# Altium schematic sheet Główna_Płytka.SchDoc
size A0; SheetNumber: 1; SheetTotal: 1
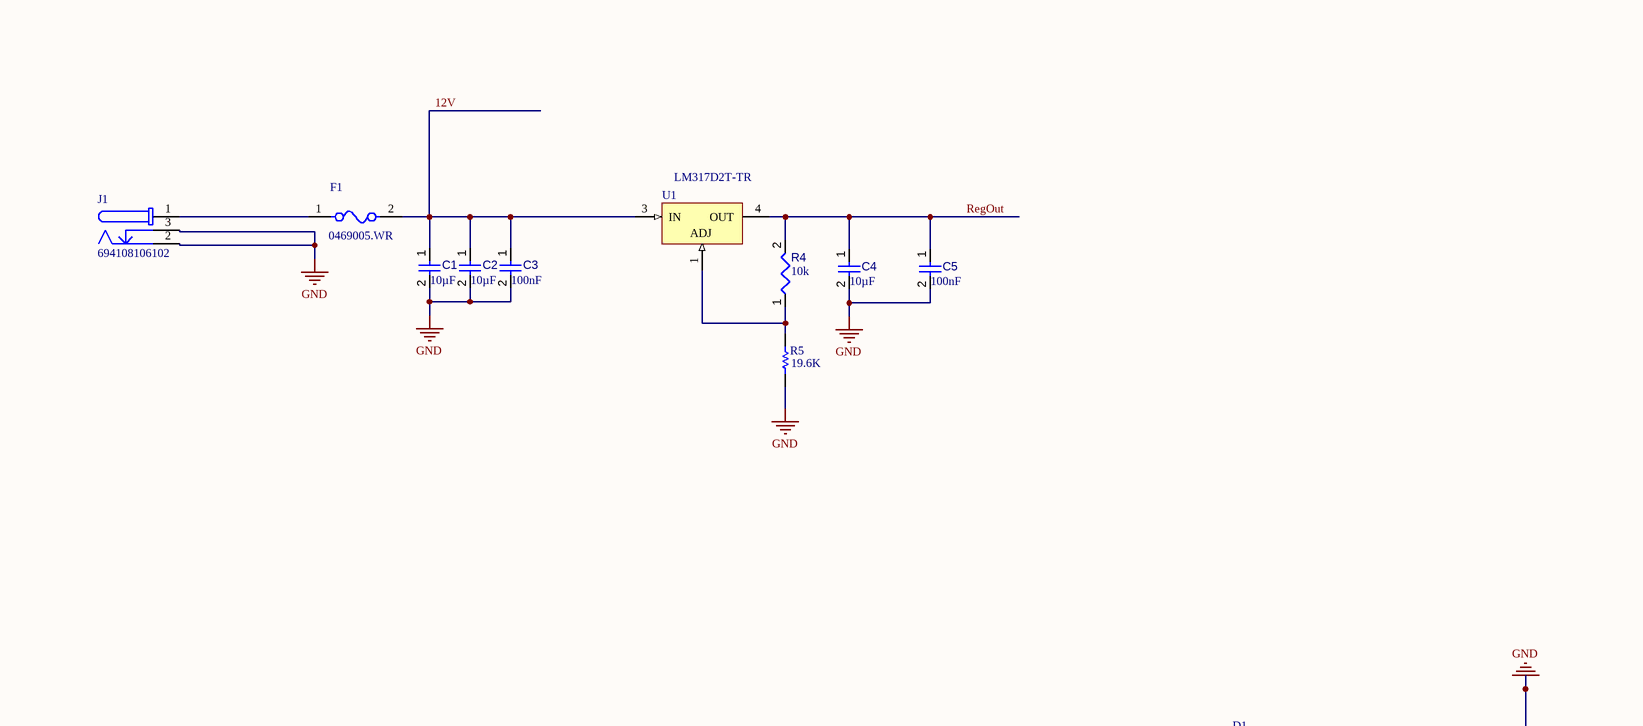
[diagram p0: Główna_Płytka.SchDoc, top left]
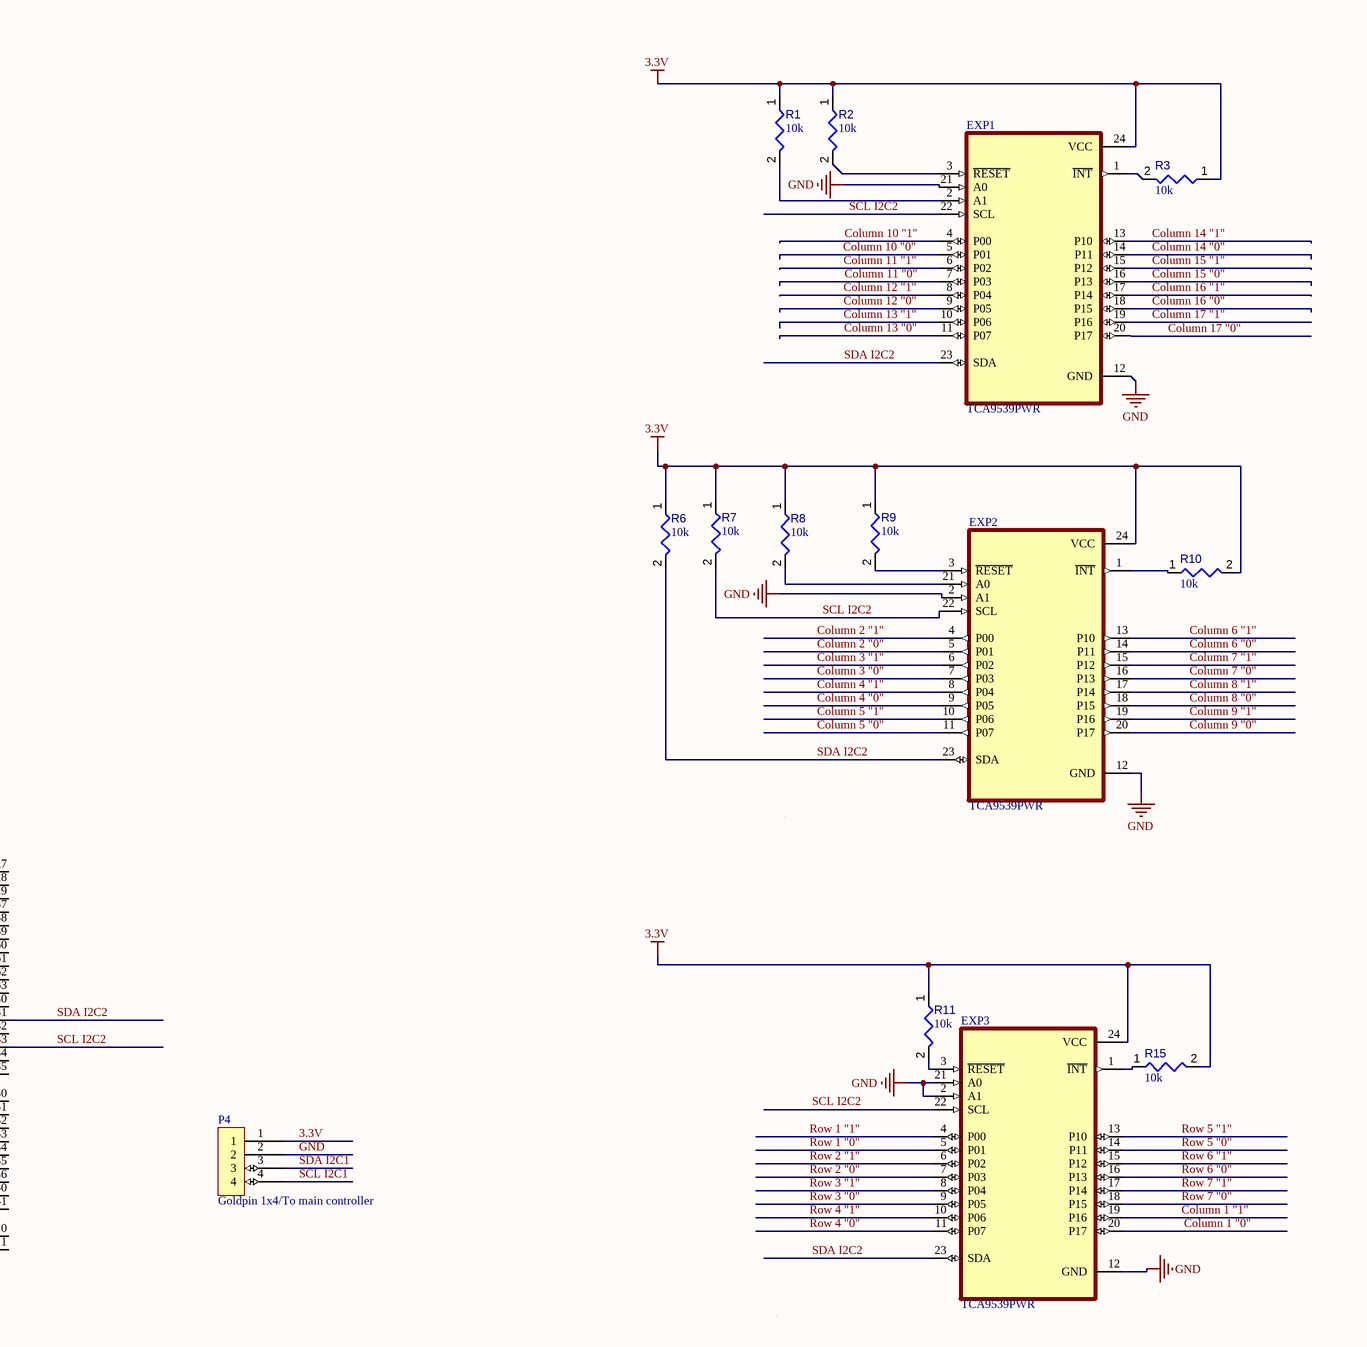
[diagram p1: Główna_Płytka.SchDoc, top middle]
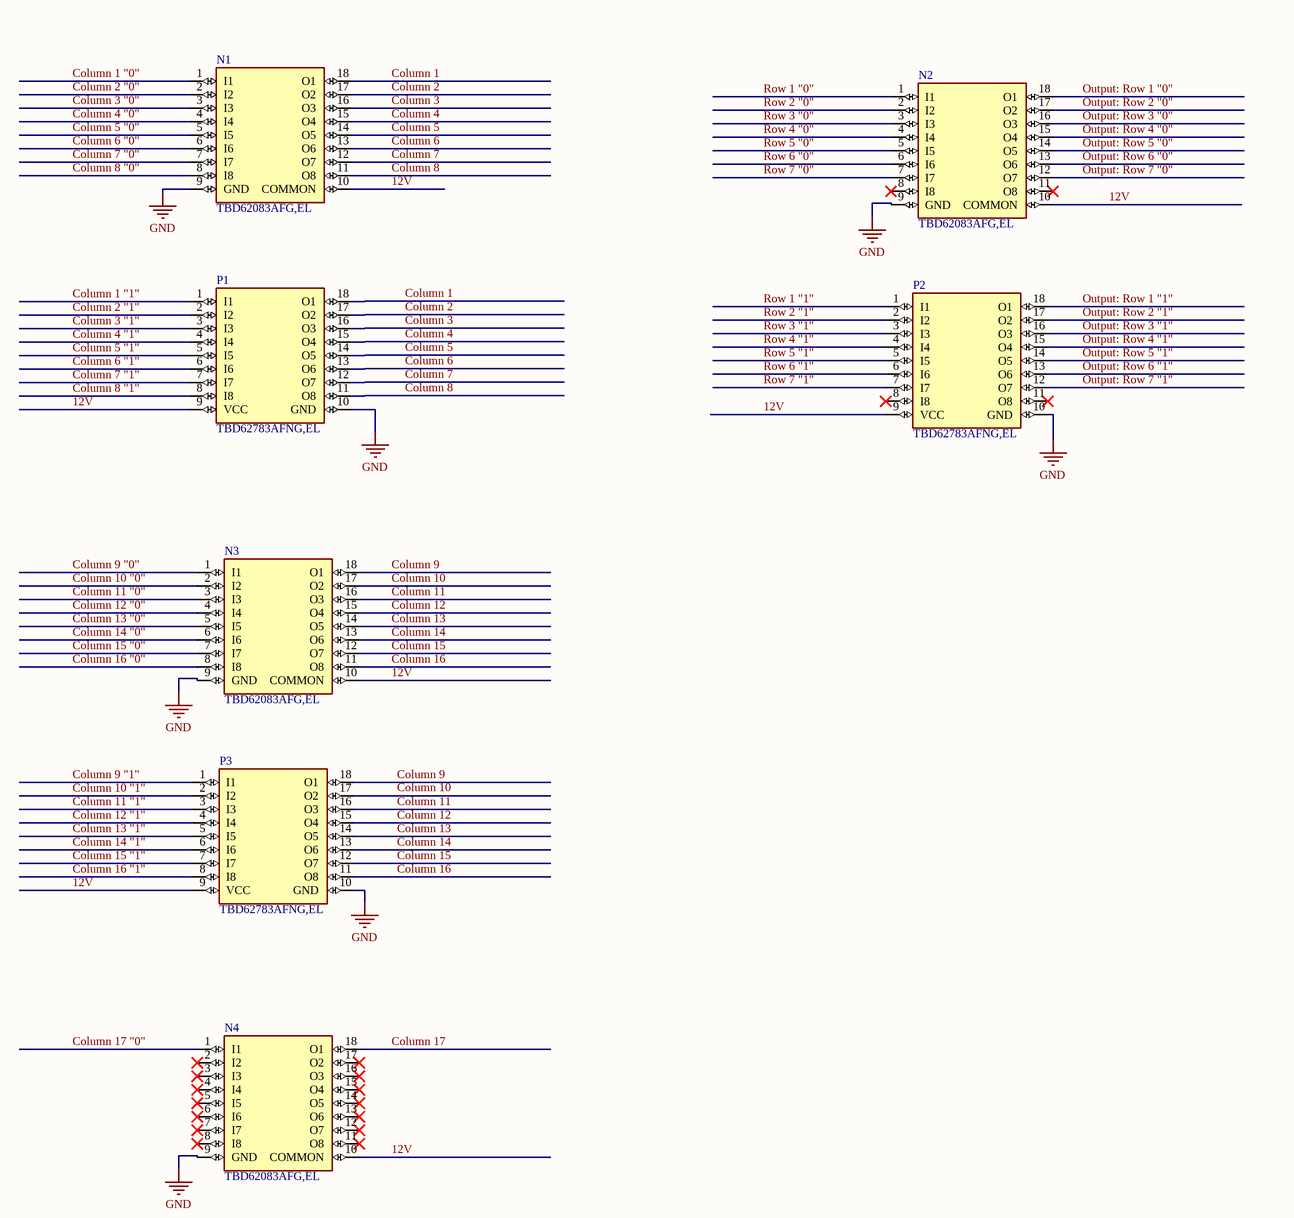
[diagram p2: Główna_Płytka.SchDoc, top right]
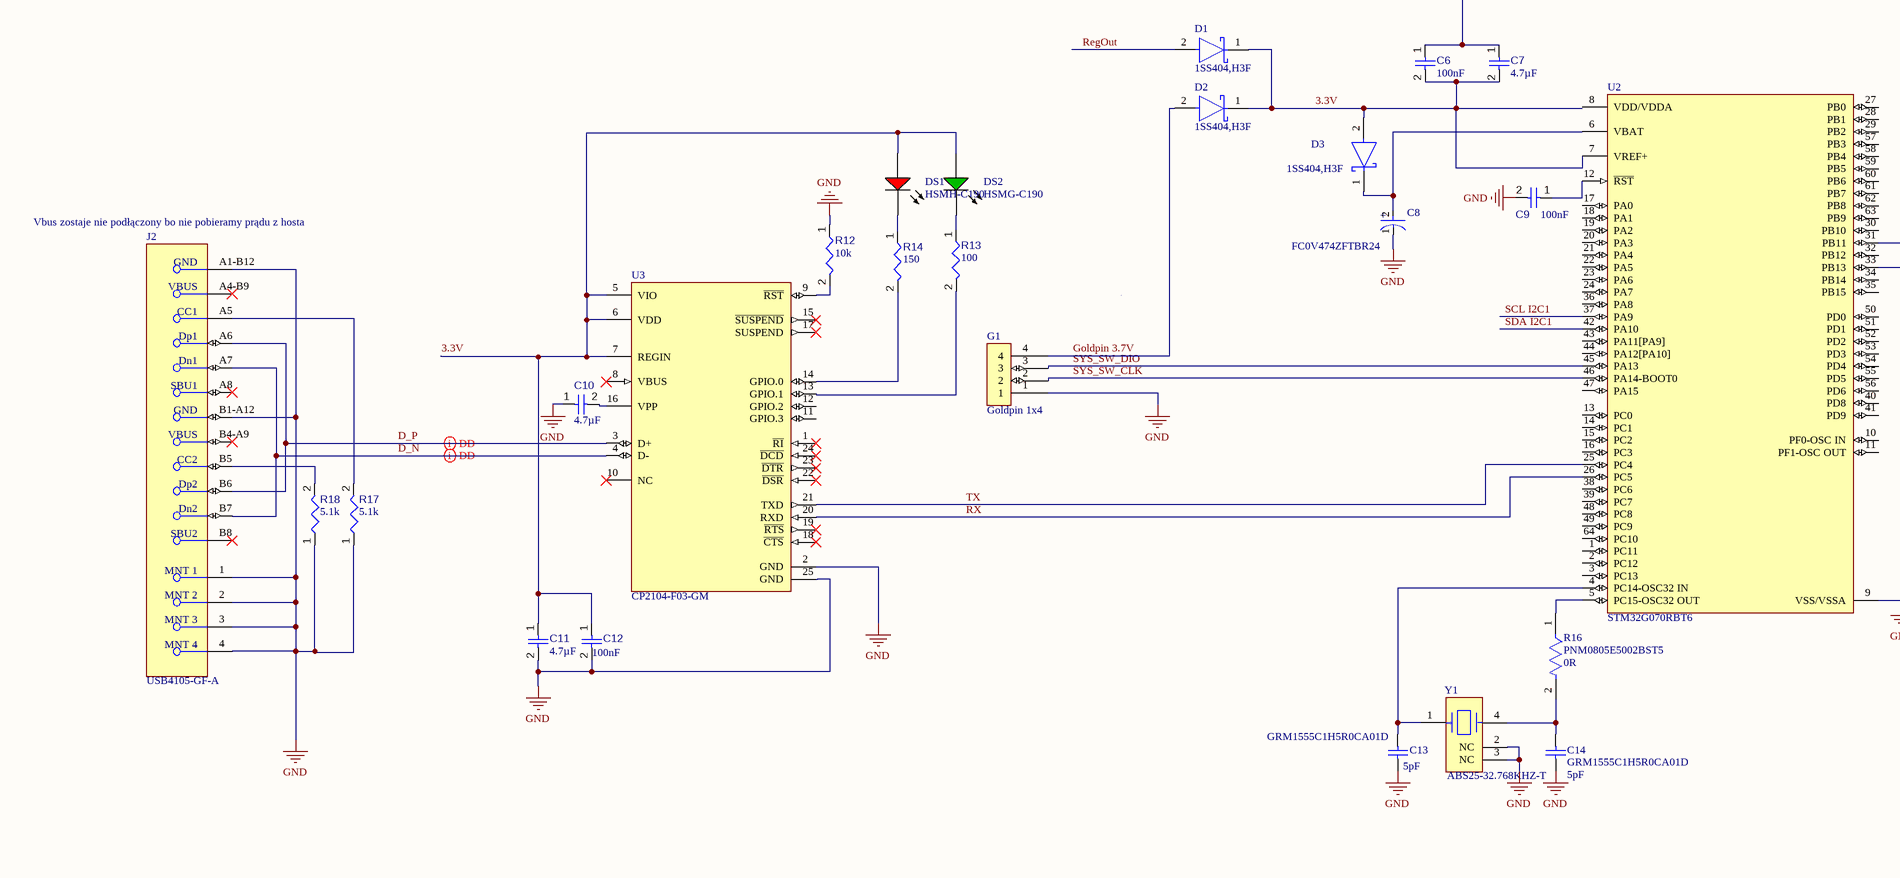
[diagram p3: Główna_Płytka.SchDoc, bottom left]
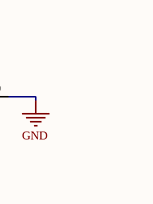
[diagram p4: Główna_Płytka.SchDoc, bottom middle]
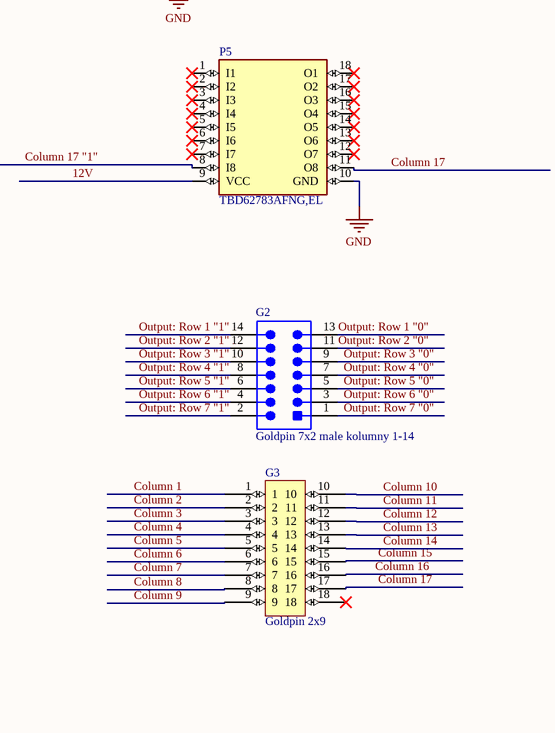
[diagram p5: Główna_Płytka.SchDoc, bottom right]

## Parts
C1  value 10µF  [CAPC0603(1608)100_L]  (hidden comment: Capacitor 10µF +/-20% 10V 0603)
C2  value 10µF  [CAPC0603(1608)100_L]  (hidden comment: Capacitor 10µF +/-20% 10V 0603)
C3  value 100nF  [CAPC0402(1005)60_L]  (hidden comment: Capacitor 100nF +/-20% 50V 0402)
C4  value 10µF  [CAPC0603(1608)100_L]  (hidden comment: Capacitor 10µF +/-20% 10V 0603)
C5  value 100nF  [CAPC0402(1005)60_L]  (hidden comment: Capacitor 100nF +/-20% 50V 0402)
C6  value 100nF  [CAPC0402(1005)60_L]  (hidden comment: Capacitor 100nF +/-20% 10V 0402)
C7  value 4.7µF  [CAPC0603(1608)100_L]  (hidden comment: Capacitor 4.7µF +/-20% 10V 0603)
C8  FC0V474ZFTBR24  [FP-FC0V474ZFTBR24-MFG]
C9  value 100nF  [CAPC0402(1005)60_L]  (hidden comment: Capacitor 100nF +/-20% 50V 0402)
C10  value 4.7µF  [CAPC0603(1608)100_L]  (hidden comment: Capacitor 4.7µF +/-20% 10V 0603)
C11  value 4.7µF  [CAPC0603(1608)100_L]  (hidden comment: Capacitor 4.7µF +/-20% 10V 0603)
C12  value 100nF  [CAPC0402(1005)60_L]  (hidden comment: Capacitor 100nF +/-20% 50V 0402)
C13  GRM1555C1H5R0CA01D  value 5pF  [CAPC1005X55X25LL05T10]
C14  GRM1555C1H5R0CA01D  value 5pF  [CAPC1005X55X25LL05T10]
D1  1SS404,H3F  [FP-SOD-323-MFG]
D2  1SS404,H3F  [FP-SOD-323-MFG]
D3  1SS404,H3F  [FP-SOD-323-MFG]
DS1  HSMH-C190  [AVAG-HSMX-C190_V]
DS2  HSMG-C190  [AVAG-HSMX-C190_V]
EXP1  TCA9539PWR  [SOP65P640X120-24N]
EXP2  TCA9539PWR  [SOP65P640X120-24N]
EXP3  TCA9539PWR  [SOP65P640X120-24N]
F1  0469005.WR  [FP-0469-MFG]
G1  Goldpin 1x4  [Goldpin 1x4-Footprint-1]
G2  Goldpin 7x2 male kolumny 1-14  [HRWN-M20-9980745_V]
G3  Goldpin 2x9  [Goldpin 2x9-Footprint-1]
J1  694108106102  [694108106102]
J2  USB4105-GF-A  [FP-USB4105-GF-A-MFG]
N1  TBD62083AFG,EL  [SOIC127P1030X245-18N]
N2  TBD62083AFG,EL  [SOIC127P1030X245-18N]
N3  TBD62083AFG,EL  [SOIC127P1030X245-18N]
N4  TBD62083AFG,EL  [SOIC127P1030X245-18N]
P1  TBD62783AFNG,EL  [New footprint 1]
P2  TBD62783AFNG,EL  [New footprint 1]
P3  TBD62783AFNG,EL  [New footprint 1]
P4  Goldpin 1x4/To main controller  [Goldpin 1x4-Footprint-1]
P5  TBD62783AFNG,EL  [New footprint 1]
R1  value 10k  [RESC2013X50X35ML15T15]  (hidden comment: Resistor 10k +/-1% 0805 125 mW)
R2  value 10k  [RESC2013X50X35ML15T15]  (hidden comment: Resistor 10k +/-1% 0805 125 mW)
R3  value 10k  [RESC2013X50X35ML15T15]  (hidden comment: Resistor 10k +/-1% 0805 125 mW)
R4  value 10k  [RESC2013X50X35ML15T15]  (hidden comment: Resistor 10k +/-1% 0805 125 mW)
R5  value 19.6K  [RESC1005X40X25NL05T05]  (hidden comment: ERJ-2RKF1962X)
R6  value 10k  [RESC2013X50X35ML15T15]  (hidden comment: Resistor 10k +/-1% 0805 125 mW)
R7  value 10k  [RESC2013X50X35ML15T15]  (hidden comment: Resistor 10k +/-1% 0805 125 mW)
R8  value 10k  [RESC2013X50X35ML15T15]  (hidden comment: Resistor 10k +/-1% 0805 125 mW)
R9  value 10k  [RESC2013X50X35ML15T15]  (hidden comment: Resistor 10k +/-1% 0805 125 mW)
R10  value 10k  [RESC2013X50X35ML15T15]  (hidden comment: Resistor 10k +/-1% 0805 125 mW)
R11  value 10k  [RESC2013X50X35ML15T15]  (hidden comment: Resistor 10k +/-1% 0805 125 mW)
R12  value 10k  [RESC2013X50X35ML15T15]  (hidden comment: Resistor 10k +/-1% 0805 125 mW)
R13  value 100  [RESC2013X50X35ML15T15]  (hidden comment: Resistor 10k +/-1% 0805 125 mW)
R14  value 150  [RESC2013X50X35ML15T15]  (hidden comment: Resistor 10k +/-1% 0805 125 mW)
R15  value 10k  [RESC2013X50X35ML15T15]  (hidden comment: Resistor 10k +/-1% 0805 125 mW)
R16  PNM0805E5002BST5  Resistance: 0R  [FP-PNM0805-MFG]
R17  value 5.1k  [RESC2013X50X35ML15T15]  (hidden comment: Resistor 10k +/-1% 0805 125 mW)
R18  value 5.1k  [RESC2013X50X35ML15T15]  (hidden comment: Resistor 10k +/-1% 0805 125 mW)
U1  LM317D2T-TR  [TO-263_N]
U2  STM32G070RBT6  [FP-LQFP64-5W-MFG]
U3  CP2104-F03-GM  [FP-CP2104-F03-GM-MFG]
Y1  ABS25-32.768KHZ-T  [FP-ABS25-MFG]

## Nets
3.3V: C6.2 C7.2 C11.1 C12.1 D1.1(C) D2.1(C) D3.2(A) DS1.1(A) DS2.1(A) EXP1.24(VCC) EXP2.24(VCC) EXP3.24(VCC) P4.1 R1.1 R2.1 R3.1 R6.1 R7.1 R8.1 R9.1 R10.2 R11.1 R15.2 U2.7(VREF+) U3.5(VIO) U3.6(VDD) U3.7(REGIN)
GND: C1.2 C2.2 C3.2 C4.2 C5.2 C6.1 C7.1 C8.1(C) C9.2 C10.1 C11.2 C12.2 C13.1 C14.1 EXP1.12(GND) EXP1.21(A0) EXP2.2(A1) EXP2.12(GND) EXP3.2(A1) EXP3.12(GND) EXP3.21(A0) G1.1 J1.2 J1.3 J2.1(MNT_1) J2.2(MNT_2) J2.3(MNT_3) J2.4(MNT_4) J2.A1-B12(GND) J2.B1-A12(GND) N1.9(GND) N2.9(GND) N3.9(GND) N4.9(GND) P1.10(GND) P2.10(GND) P3.10(GND) P4.2 P5.10(GND) R5.2 R12.1 R17.1 R18.1 U2.9(VSS/VSSA) U3.2(GND) U3.25(GND) Y1.2(NC) Y1.3(NC)
12V: C1.1 C2.1 C3.1 F1.2 N1.10(COMMON) N2.10(COMMON) N3.10(COMMON) N4.10(COMMON) P1.9(VCC) P2.9(VCC) P3.9(VCC) P5.9(VCC) U1.3(IN)
Column 1: G3.1 N1.18(O1) P1.18(O1)
Column 1 "0": EXP3.20(P17) N1.1(I1)
Column 1 "1": EXP3.19(P16) P1.1(I1)
Column 2: G3.2 N1.17(O2) P1.17(O2)
Column 2 "0": EXP2.5(P01) N1.2(I2)
Column 2 "1": EXP2.4(P00) P1.2(I2)
Column 3: G3.3 N1.16(O3) P1.16(O3)
Column 3 "0": EXP2.7(P03) N1.3(I3)
Column 3 "1": EXP2.6(P02) P1.3(I3)
Column 4: G3.4 N1.15(O4) P1.15(O4)
Column 4 "0": EXP2.9(P05) N1.4(I4)
Column 4 "1": EXP2.8(P04) P1.4(I4)
Column 5: G3.5 N1.14(O5) P1.14(O5)
Column 5 "0": EXP2.11(P07) N1.5(I5)
Column 5 "1": EXP2.10(P06) P1.5(I5)
Column 6: G3.6 N1.13(O6) P1.13(O6)
Column 6 "0": EXP2.14(P11) N1.6(I6)
Column 6 "1": EXP2.13(P10) P1.6(I6)
Column 7: G3.7 N1.12(O7) P1.12(O7)
Column 7 "0": EXP2.16(P13) N1.7(I7)
Column 7 "1": EXP2.15(P12) P1.7(I7)
Column 8: G3.8 N1.11(O8) P1.11(O8)
Column 8 "0": EXP2.18(P15) N1.8(I8)
Column 8 "1": EXP2.17(P14) P1.8(I8)
Column 9: G3.9 N3.18(O1) P3.18(O1)
Column 9 "0": EXP2.20(P17) N3.1(I1)
Column 9 "1": EXP2.19(P16) P3.1(I1)
Column 10: G3.10 N3.17(O2) P3.17(O2)
Column 10 "0": EXP1.5(P01) N3.2(I2)
Column 10 "1": EXP1.4(P00) P3.2(I2)
Column 11: G3.11 N3.16(O3) P3.16(O3)
Column 11 "0": EXP1.7(P03) N3.3(I3)
Column 11 "1": EXP1.6(P02) P3.3(I3)
Column 12: G3.12 N3.15(O4) P3.15(O4)
Column 12 "0": EXP1.9(P05) N3.4(I4)
Column 12 "1": EXP1.8(P04) P3.4(I4)
Column 13: G3.13 N3.14(O5) P3.14(O5)
Column 13 "0": EXP1.11(P07) N3.5(I5)
Column 13 "1": EXP1.10(P06) P3.5(I5)
Column 14: G3.14 N3.13(O6) P3.13(O6)
Column 14 "0": EXP1.14(P11) N3.6(I6)
Column 14 "1": EXP1.13(P10) P3.6(I6)
Column 15: G3.15 N3.12(O7) P3.12(O7)
Column 15 "0": EXP1.16(P13) N3.7(I7)
Column 15 "1": EXP1.15(P12) P3.7(I7)
Column 16: G3.16 N3.11(O8) P3.11(O8)
Column 16 "0": EXP1.18(P15) N3.8(I8)
Column 16 "1": EXP1.17(P14) P3.8(I8)
Column 17: G3.17 N4.18(O1) P5.11(O8)
Column 17 "0": EXP1.20(P17) N4.1(I1)
Column 17 "1": EXP1.19(P16) P5.8(I8)
D_N: J2.A7(Dn1) J2.B7(Dn2) U3.4(D-)
D_P: J2.A6(Dp1) J2.B6(Dp2) U3.3(D+)
Goldpin 3.7V: D2.2(A) G1.4
Output: Row 1 "0": G2.13 N2.18(O1)
Output: Row 1 "1": G2.14 P2.18(O1)
Output: Row 2 "0": G2.11 N2.17(O2)
Output: Row 2 "1": G2.12 P2.17(O2)
Output: Row 3 "0": G2.9 N2.16(O3)
Output: Row 3 "1": G2.10 P2.16(O3)
Output: Row 4 "0": G2.7 N2.15(O4)
Output: Row 4 "1": G2.8 P2.15(O4)
Output: Row 5 "0": G2.5 N2.14(O5)
Output: Row 5 "1": G2.6 P2.14(O5)
Output: Row 6 "0": G2.3 N2.13(O6)
Output: Row 6 "1": G2.4 P2.13(O6)
Output: Row 7 "0": G2.1 N2.12(O7)
Output: Row 7 "1": G2.2 P2.12(O7)
RegOut: C4.1 C5.1 D1.2(A) R4.2 U1.4(OUT)
Row 1 "0": EXP3.5(P01) N2.1(I1)
Row 1 "1": EXP3.4(P00) P2.1(I1)
Row 2 "0": EXP3.7(P03) N2.2(I2)
Row 2 "1": EXP3.6(P02) P2.2(I2)
Row 3 "0": EXP3.9(P05) N2.3(I3)
Row 3 "1": EXP3.8(P04) P2.3(I3)
Row 4 "0": EXP3.11(P07) N2.4(I4)
Row 4 "1": EXP3.10(P06) P2.4(I4)
Row 5 "0": EXP3.14(P11) N2.5(I5)
Row 5 "1": EXP3.13(P10) P2.5(I5)
Row 6 "0": EXP3.16(P13) N2.6(I6)
Row 6 "1": EXP3.15(P12) P2.6(I6)
Row 7 "0": EXP3.18(P15) N2.7(I7)
Row 7 "1": EXP3.17(P14) P2.7(I7)
RX: U2.26(PC5) U3.20(RXD)
SCL I2C1: P4.4 U2.37(PA9)
SCL I2C2: EXP1.22(SCL) EXP2.22(SCL) EXP3.22(SCL) R7.2 U2.33(PB13)
SDA I2C1: P4.3 U2.42(PA10)
SDA I2C2: EXP1.23(SDA) EXP2.23(SDA) EXP3.23(SDA) R6.2 U2.31(PB11)
SYS_SW_CLK: G1.2 U2.46(PA14-BOOT0)
SYS_SW_DIO: G1.3 U2.45(PA13)
TX: U2.25(PC4) U3.21(TXD)
NetC8_2: C8.2(A) D3.1(C) U2.6(VBAT)
NetC9_1: C9.1 U2.12(~{RST})
NetC10_2: C10.2 U3.16(VPP)
NetC13_2: C13.2 U2.4(PC14-OSC32_IN) Y1.1
NetC14_2: C14.2 R16.2 Y1.4
NetDS1_2: DS1.2(K) R14.1
NetDS2_2: DS2.2(K) R13.1
NetEXP1_1: EXP1.1(~{INT}) R3.2
NetEXP1_2: EXP1.2(A1) R1.2
NetEXP1_3: EXP1.3(~{RESET}) R2.2
NetEXP2_1: EXP2.1(~{INT}) R10.1
NetEXP2_3: EXP2.3(~{RESET}) R9.2
NetEXP2_21: EXP2.21(A0) R8.2
NetEXP3_1: EXP3.1(~{INT}) R15.1
NetEXP3_3: EXP3.3(~{RESET}) R11.2
NetF1_1: F1.1 J1.1
NetJ2_A5: J2.A5(CC1) R17.2
NetJ2_B5: J2.B5(CC2) R18.2
NetR4_1: R4.1 R5.1 U1.1(ADJ)
NetR12_2: R12.2 U3.9(~{RST})
NetR13_2: R13.2 U3.13(GPIO.1)
NetR14_2: R14.2 U3.14(GPIO.0)
NetR16_1: R16.1 U2.5(PC15-OSC32_OUT)

Not connected (* = marked no-connect by the designer): G3 18*; J2 A4-B9(VBUS)* A8(SBU1)* B4-A9(VBUS)* B8(SBU2)*; N2 8(I8)* 11(O8)*; N4 2(I2)* 3(I3)* 4(I4)* 5(I5)* 6(I6)* 7(I7)* 8(I8)* 11(O8)* 12(O7)* 13(O6)* 14(O5)* 15(O4)* 16(O3)* 17(O2)*; P2 8(I8)* 11(O8)*; P5 1(I1)* 2(I2)* 3(I3)* 4(I4)* 5(I5)* 6(I6)* 7(I7)* 12(O7)* 13(O6)* 14(O5)* 15(O4)* 16(O3)* 17(O2)* 18(O1)*; U2 1(PC11) 2(PC12) 3(PC13) 8(VDD/VDDA) 10(PF0-OSC_IN) 11(PF1-OSC_OUT) 13(PC0) 14(PC1) 15(PC2) 16(PC3) 17(PA0) 18(PA1) 19(PA2) 20(PA3) 21(PA4) 22(PA5) 23(PA6) 24(PA7) 27(PB0) 28(PB1) 29(PB2) 30(PB10) 32(PB12) 34(PB14) 35(PB15) 36(PA8) 38(PC6) 39(PC7) 40(PD8) 41(PD9) 43(PA11[PA9]) 44(PA12[PA10]) 47(PA15) 48(PC8) 49(PC9) 50(PD0) 51(PD1) 52(PD2) 53(PD3) 54(PD4) 55(PD5) 56(PD6) 57(PB3) 58(PB4) 59(PB5) 60(PB6) 61(PB7) 62(PB8) 63(PB9) 64(PC10); U3 1(~{RI})* 8(VBUS)* 10(NC)* 11(GPIO.3) 12(GPIO.2) 15(~{SUSPEND})* 17(SUSPEND)* 18(~{CTS})* 19(~{RTS})* 22(~{DSR})* 23(~{DTR})* 24(~{DCD})*

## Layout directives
differential pair: D_N, D_P

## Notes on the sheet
- (near J2) Vbus zostaje nie podłączony bo nie pobieramy prądu z hosta

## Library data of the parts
C1 C2 C4 = CMP-001-00075-4: Chip Capacitor, 10µF +/-20%, 10V, 0603, Thickness 1 mm; Tolerance: 10%
C3 C5 C9 C12 = CMP-001-00067-3: Chip Capacitor, 100nF +/-20%, 50V, 0402, Thickness 0.6 mm; Tolerance: 10%
C6 = CMP-001-00061-3: Chip Capacitor, 100nF +/-20%, 10V, 0402, Thickness 0.6 mm; Tolerance: 20%
C7 C10 C11 = CMP-001-00076-4: Chip Capacitor, 4.7µF +/-20%, 10V, 0603, Thickness 1 mm; Tolerance: 10%
C8 = CMP-03024-000007-1: CAP 470mF -20% +80% 3.5V SMD; ESR (Equivalent Series Resistance): 25R; Leakage Current: 420uA; Tolerance: 80%
C13 C14 = CMP-2008-04391-1: Manufacturer: Murata
D1-D3 = CMP-35905-000002-1: DIODE SCHOTTKY 20V 300MA USC; Max Repetitive Reverse Voltage (Vrrm): 25V; Element Configuration: Single
DS1 = CMP-007-00014-2: LED Uni-Color Red, 65 mW, 20 mA, -40 to 85 degC, 2-Pin SMD, RoHS, Tape and Reel; Manufacturer: Avago; Nominal Vf: 1.8V; Luminous Intensity: 17mcd; Power: 78mW; Forward Current: 20mA; Lens Style: Diffused; Viewing Angle: 170degrees
DS2 = CMP-007-00013-2: LED Uni-Color Green, 52 mW, 20 mA, -40 to 85 degC, 2-Pin SMD, RoHS, Tape and Reel; Manufacturer: Avago; Forward Current: 20mA; Viewing Angle: 170degrees; Luminous Intensity: 15mcd; Lens Style: Diffused; Forward Voltage: 2.2V; Power: 52mW
EXP1-EXP3 = CMP-012-000001-2: Remote 16-Bit I2C and SMBus Low-Power I/O Expander w/ Interrupt Output, Reset, and Config Registers 24-TSSOP -40 to 85; MF: Texas Instruments
F1 = CMP-08605-000100-1: FUSE BOARD MOUNT 5A 32VDC 1206; Approvals: UL; Voltage Rating (DC): 32V; Blow Characteristic: TIME DELAY; DC Cold Resistance: 35mR; Power Dissipation: 1.08W; Fuse Type: Board Mount (Cartridge Style Excluded); Body Material: Ceramic
G1 = CMP-002-00078-3: Goldpin, connector, 1 row 4 pin
G2 = CMP-002-00076-1: 2 - kolumna 1 EXP1 / 4 - kolumna 2 / 6 - kolumna 3 / 8 - kolumna 4 / ... etc / 1 - kolumna 8 / 3 - kolumna 9; Connector Type: BOARD CONNECTOR
G3 = CMP-002-00079-1: Goldpin, connector, 2 row 9 pin
J1 = CMP-1502-00180-2: NexarPartId: 52645186; Shielding: Unshielded; Voltage Rating: 24V; Connector Type: Power; Insulation Resistance: 100MΩ; Current Rating: 5A; Gender: Male
J2 = CMP-245163-000001-1: CONN RCPT USB2.0 TYPEC 5A; Manufacturer: GCT; Voltage Rating: 20V; Is Female: yes; Current Rating: 5/6.25/1.25/0.25A; Number Of Contacts: 16; Conn Orientation: Right Angle
N1 = CMP-011-00013-3: Power Switch/Driver 1:1 N-Channel 500mA 18-SOP / Buffer/Inverter Based Peripheral Driver, 8 Driver, 0.4A, BCD, PDSO18 / ****************************************TUTAJ*************************************** / 1 - / 2 - PA1 - kolumna 10 "0" / 3 - / 4 - PA3 kolumna 11 "0" / 5 - / 6 - PA5 kolumna 12 "0 / 7 - / 8 - PA7 kolumna 13 "0"; MF: Toshiba Semiconductor
N2-N4 = CMP-011-00013-3: Power Switch/Driver 1:1 N-Channel 500mA 18-SOP; MF: Toshiba Semiconductor
P1 = CMP-006-00021-2: Buffer/Inverter Based Peripheral Driver, 8 Driver, 0.4A, BCD, PDSO18 / ****************************************TUTAJ*************************************** / 1 - / 2 - / 3 - / 4 - / 5 - / 6 - / 7 - / 8 -
P2 P3 P5 = CMP-006-00021-2: Buffer/Inverter Based Peripheral Driver, 8 Driver, 0.4A, BCD, PDSO18
P4 = CMP-002-00078-2: Goldpin, connector, 1 row 4 pin
R1-R4 R6-R15 R17 R18 = CMP-009-00018-5: Chip Resistor, 10 KOhm, +/- 1%, 125 mW, -55 to 155 degC, 0805 (2012 Metric); Power: 125mW; Voltage Rating: 150V
R5 = CMP-1011-00654-2: Manufacturer: Panasonic
R16 = CMP-02407-012955-1: RES SMD 50K OHM 0.1% 1/5W 0805 / //0 R aby był footprint i wytłumić raczej nieprawdopodobne wyższe harmoniczne; Power Rating: 200mW; Temperature Coefficient: 25ppm/°C; Voltage Rating (DC): 100V
U1 = CMP-0244-00094-1: 1.5A, 1.2V to 37V Adjustable Voltage Regulator, 3-Pin D2PAK, Tape and Reel
U2 = CMP-12105-000143-1: IC MCU 32BIT 128KB FLASH 64LQFP
U3 = CMP-0511-00004-2: IC SGL USB-TO-UART BRIDGE 24QFN; Number of Transceivers: 1; Max Supply Voltage: 3.6V; Operating Supply Current: 17mA; Operating Supply Voltage: 3.3V; Data Rate: 2Mbps; Min Supply Voltage: 3V
Y1 = CMP-2000-05037-2: CRYSTAL 32.7680KHZ 12.5PF SMD; ESR (Equivalent Series Resistance): 50kR; Tolerance: 20ppm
